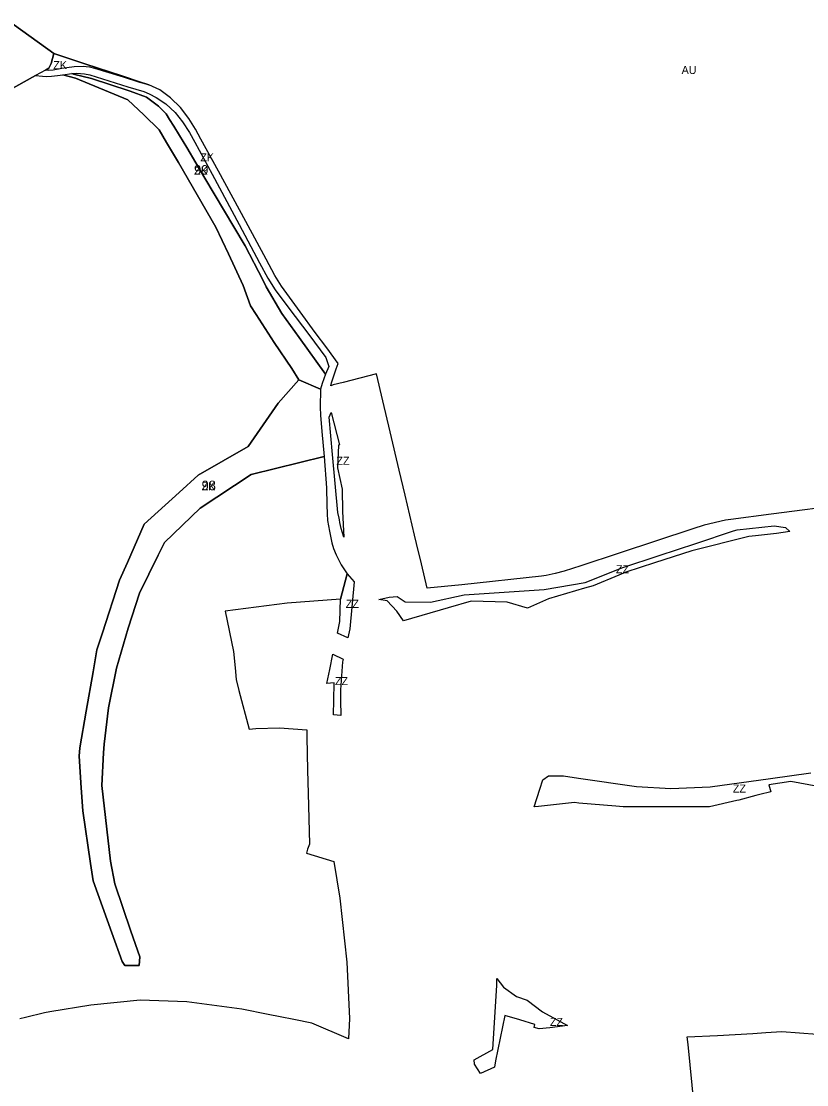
# Model space of a CAD drawing. Extents: x -535894 to -532834, y -1165802 to -1163647.
# Drawn here: x -534838 to -534347, y -1165127 to -1164462 of the extents above; entities that cross this region are included whole.
import ezdxf

# ---------------------------------------------------------------- set-up
doc = ezdxf.new("R2010")
doc.units = 0
for name, color, linetype in [('Vrstva 10', 7, 'Continuous'), ('Vrstva 16', 7, 'Continuous'), ('Vrstva 17', 7, 'Continuous'), ('Vrstva 19', 7, 'Continuous'), ('Vrstva 22', 7, 'Continuous'), ('Vrstva 61', 7, 'Continuous')]:
    doc.layers.add(name, color=color, linetype=linetype)

msp = doc.modelspace()

# ---------------------------------------------------------------- linework, layer by layer
at = {"layer": 'Vrstva 10'}
for points in [[(-534636.46, -1164784.72), (-534638.064, -1164779.14), (-534638.852, -1164775.393), (-534639.176, -1164773.814), (-534639.373, -1164772.852), (-534640.098, -1164769.323), (-534643.475, -1164733.089), (-534645.604, -1164709.726), (-534644.26, -1164706.72), (-534639.15, -1164726.91), (-534639.68, -1164727.13), (-534640.39, -1164741.43), (-534637.48, -1164754.64), (-534637.31, -1164768.51)], [(-534360.697, -1164778.681), (-534357.919, -1164781.042), (-534366.34, -1164782.38), (-534379.47, -1164783.81), (-534383.65, -1164784.27), (-534419.24, -1164793.21), (-534442.43, -1164800.73), (-534460.33, -1164806.54), (-534464.74, -1164808.35), (-534480.71, -1164814.95), (-534486.09, -1164816.51), (-534508.57, -1164823.07), (-534521.8, -1164828.99), (-534534.47, -1164825.11), (-534557.01, -1164824.52), (-534571.19, -1164828.66), (-534599.08, -1164836.8), (-534603.3, -1164830.84), (-534609.45, -1164824.46), (-534614.56, -1164823.48), (-534608.112, -1164822.093), (-534603.04, -1164821.677), (-534598.14, -1164825.08), (-534582.32, -1164825.13), (-534561.27, -1164820.66), (-534511.37, -1164817.22), (-534485.79, -1164812.88), (-534462.18, -1164803.59), (-534439.58, -1164796.11), (-534428.15, -1164792.33), (-534416.78, -1164788.57), (-534393.08, -1164780.73), (-534390.78, -1164779.97), (-534367.86, -1164777.52)], [(-534634.384, -1164807.473), (-534629.933, -1164812.5), (-534632.65, -1164841.86), (-534633.89, -1164847.539), (-534640.463, -1164844.555), (-534638.93, -1164837.28), (-534638.54, -1164823.25)], [(-534638.31, -1164895.93), (-534642.85, -1164895.55), (-534642.66, -1164886.34), (-534642.44, -1164875.67), (-534647.08, -1164876), (-534645.23, -1164867.21), (-534643.23, -1164857.71), (-534636.791, -1164860.825), (-534637.156, -1164862.496), (-534638.46, -1164879.942), (-534638.46, -1164886.69)], [(-534541.67, -1165111.7), (-534542.44, -1165115.58), (-534551, -1165119.46), (-534554.9, -1165113.66), (-534555.08, -1165111.1), (-534543.46, -1165104.62), (-534540.87, -1165064.35), (-534540.96, -1165060.2), (-534536.786, -1165065.584), (-534528.58, -1165071.39), (-534522.06, -1165073.71), (-534512.37, -1165081.09), (-534496.832, -1165089.669), (-534507.77, -1165091), (-534514.4, -1165091.6), (-534517.52, -1165090.78), (-534517.17, -1165088.92), (-534526.65, -1165086.13), (-534535.98, -1165083.39)]]:
    msp.add_lwpolyline(points, close=True, dxfattribs=at)
msp.add_lwpolyline([(-534334.97, -1164941.39), (-534357.43, -1164937.18), (-534371.08, -1164939.34), (-534369.96, -1164943.59), (-534376.73, -1164945.38), (-534379.25, -1164946.03), (-534389.78, -1164948.76), (-534391.17, -1164949.12), (-534408.23, -1164953), (-534422.33, -1164953), (-534431.79, -1164953.01), (-534436.16, -1164953), (-534443.26, -1164953), (-534445.31, -1164953), (-534462.09, -1164953), (-534466.57, -1164952.61), (-534489.63, -1164950.63), (-534492.39, -1164950.39), (-534514.81, -1164952.71), (-534517.7, -1164953.01), (-534513.989, -1164941.981), (-534512.197, -1164936.183), (-534508.626, -1164933.758), (-534499.188, -1164933.763), (-534489.849, -1164935.129), (-534453.798, -1164940.399), (-534432.188, -1164941.664), (-534407.72, -1164940.465), (-534369.994, -1164935.234), (-534344.906, -1164931.755)], dxfattribs=at)
at = {"layer": 'Vrstva 16'}
for points in [[(-534812.44, -1164492.038), (-534817.869, -1164493.052), (-534820.49, -1164493.143), (-534822.728, -1164493.033), (-534820.5, -1164491.79), (-534819.12, -1164488.91), (-534817.509, -1164482.62), (-534798.087, -1164488.983), (-534774.321, -1164496.768), (-534763.983, -1164500.339), (-534758.097, -1164502.081), (-534763.833, -1164500.668), (-534774.034, -1164497.362), (-534791.926, -1164491.894), (-534795.044, -1164491.154), (-534797.225, -1164490.889), (-534799.185, -1164490.795), (-534804.682, -1164491.006)], [(-534645.847, -1164677.959), (-534647.904, -1164682.84), (-534664.33, -1164659.93), (-534675.14, -1164644.85), (-534684.8, -1164628.21), (-534686.96, -1164624.01), (-534697.93, -1164602.7), (-534705.03, -1164590.78), (-534723.13, -1164560.41), (-534734.51, -1164541.31), (-534738.99, -1164533.78), (-534742.58, -1164527.98), (-534745.16, -1164523.82), (-534747.341, -1164520.291), (-534752.17, -1164515.41), (-534759.6, -1164509.93), (-534769.82, -1164506.09), (-534770.38, -1164505.88), (-534793.9, -1164498.24), (-534805.09, -1164495.48), (-534806.114, -1164495), (-534803.324, -1164494.852), (-534798.38, -1164495.209), (-534794.97, -1164495.874), (-534771.151, -1164503.333), (-534761.232, -1164506.36), (-534758.012, -1164507.727), (-534753.525, -1164510.08), (-534747.523, -1164514.089), (-534741.751, -1164519.514), (-534737.079, -1164525.158), (-534732.786, -1164531.828), (-534729.336, -1164538.044), (-534718.517, -1164558.022), (-534701.714, -1164589.354), (-534688.974, -1164613.292), (-534683.792, -1164622.823), (-534679.184, -1164630.139), (-534670.74, -1164641.717), (-534658.272, -1164658.05), (-534647.629, -1164672.429)]]:
    msp.add_lwpolyline(points, close=True, dxfattribs=at)
at = {"layer": 'Vrstva 17'}
for points in [[(-534650.975, -1164692.251), (-534664.512, -1164686.431), (-534668.831, -1164679.241), (-534679.849, -1164663.025), (-534691.158, -1164645.549), (-534694.624, -1164640.176), (-534699.325, -1164627.52), (-534708.387, -1164607.675), (-534716.225, -1164591.109), (-534739.693, -1164550.585), (-534747.026, -1164538.11), (-534751.669, -1164530.212), (-534761.268, -1164520.981), (-534771.301, -1164511.515), (-534803.86, -1164497.99), (-534811.888, -1164495.833), (-534806.114, -1164495), (-534805.09, -1164495.48), (-534793.9, -1164498.24), (-534770.38, -1164505.88), (-534769.82, -1164506.09), (-534759.6, -1164509.93), (-534752.17, -1164515.41), (-534747.341, -1164520.291), (-534745.16, -1164523.82), (-534742.58, -1164527.98), (-534738.99, -1164533.78), (-534734.51, -1164541.31), (-534723.13, -1164560.41), (-534705.03, -1164590.78), (-534697.93, -1164602.7), (-534686.96, -1164624.01), (-534684.8, -1164628.21), (-534675.14, -1164644.85), (-534664.33, -1164659.93), (-534647.904, -1164682.84), (-534649.925, -1164688.576)], [(-534650.975, -1164692.251), (-534651.253, -1164703.409), (-534651.057, -1164708.531), (-534650.184, -1164718.674), (-534648.645, -1164734.35), (-534694.357, -1164745.499), (-534726.198, -1164766.578), (-534748.337, -1164788.036), (-534752.217, -1164795.829), (-534764, -1164819.5), (-534770.97, -1164841.493), (-534778.305, -1164866.502), (-534783.275, -1164891.208), (-534786.064, -1164913.989), (-534786.534, -1164919.322), (-534787.471, -1164939.621), (-534782.087, -1164986.922), (-534779.471, -1165001.114), (-534769.351, -1165030.692), (-534763.686, -1165046.697), (-534764.195, -1165052.038), (-534773.14, -1165052.16), (-534774.871, -1165049.581), (-534781.343, -1165031.601), (-534792.975, -1164999.282), (-534794.582, -1164988.341), (-534799.405, -1164955.5), (-534800.386, -1164941.122), (-534801.727, -1164921.469), (-534801.157, -1164916.179), (-534797.183, -1164893.319), (-534792.919, -1164868.784), (-534790.508, -1164854.914), (-534787.074, -1164844.324), (-534776.399, -1164811.411), (-534771.546, -1164800.359), (-534761.063, -1164776.485), (-534739.279, -1164756.778), (-534727.363, -1164746), (-534696.12, -1164728), (-534677.488, -1164700.896), (-534664.512, -1164686.431)]]:
    msp.add_lwpolyline(points, close=True, dxfattribs=at)
at = {"layer": 'Vrstva 19'}
msp.add_lwpolyline([(-534866.733, -1164446.894), (-534817.509, -1164482.62), (-534819.12, -1164488.91), (-534820.5, -1164491.79), (-534822.728, -1164493.033), (-534828.796, -1164496.418), (-534893.74, -1164532.65), (-534906.91, -1164544.6), (-534916.57, -1164551.88), (-534926.03, -1164558.08), (-534936.2, -1164561.96), (-534946.31, -1164563.69), (-534957.79, -1164565.07), (-535001.64, -1164568.89), (-535054.61, -1164575.73), (-535101.2, -1164586.14), (-535117.95, -1164592.03), (-535326.28, -1164371.53)], dxfattribs=at)
at = {"layer": 'Vrstva 22'}
for points in [[(-534321.12, -1164763.995), (-534369.617, -1164770.285), (-534394.776, -1164773.547), (-534398.19, -1164773.99), (-534411.44, -1164777.13), (-534418.651, -1164779.505), (-534464.631, -1164794.65), (-534488.479, -1164802.488), (-534498.81, -1164805.87), (-534504.58, -1164807.36), (-534510.13, -1164808.51), (-534513.084, -1164808.974), (-534562.681, -1164814.447), (-534584.381, -1164816.448), (-534587.96, -1164801.37), (-534590.992, -1164788.561), (-534592.2, -1164783.46), (-534598.15, -1164758.42), (-534601.84, -1164742.85), (-534607.53, -1164718.9), (-534612.14, -1164699.44), (-534616.11, -1164682.7), (-534636.909, -1164687.961), (-534643.11, -1164689.53), (-534644.558, -1164690.047), (-534644.017, -1164688.264), (-534641.283, -1164679.593), (-534639.907, -1164676.108), (-534647.086, -1164666.492), (-534654.209, -1164656.789), (-534663.7, -1164643.954), (-534675.376, -1164627.896), (-534679.387, -1164621.172), (-534684.956, -1164611.107), (-534697.594, -1164587.582), (-534714.726, -1164556.06), (-534725.763, -1164536.1), (-534729.113, -1164529.776), (-534733.095, -1164523.114), (-534738.476, -1164516.319), (-534744.631, -1164510.374), (-534751.317, -1164505.211), (-534758.097, -1164502.081), (-534763.983, -1164500.339), (-534774.321, -1164496.768), (-534798.087, -1164488.983), (-534817.509, -1164482.62), (-534866.733, -1164446.894)], [(-534893.74, -1164532.65), (-534828.796, -1164496.418), (-534824.624, -1164496.838), (-534821.801, -1164496.902), (-534818.995, -1164496.791), (-534815.119, -1164496.425), (-534811.888, -1164495.833), (-534803.86, -1164497.99), (-534771.301, -1164511.515), (-534761.268, -1164520.981), (-534751.669, -1164530.212), (-534747.026, -1164538.11), (-534739.693, -1164550.585), (-534716.225, -1164591.109), (-534708.387, -1164607.675), (-534699.325, -1164627.52), (-534694.624, -1164640.176), (-534691.158, -1164645.549), (-534679.849, -1164663.025), (-534668.831, -1164679.241), (-534664.512, -1164686.431), (-534677.488, -1164700.896), (-534696.12, -1164728), (-534727.363, -1164746), (-534739.279, -1164756.778), (-534761.063, -1164776.485), (-534771.546, -1164800.359), (-534776.399, -1164811.411), (-534787.074, -1164844.324), (-534790.508, -1164854.914), (-534792.919, -1164868.784), (-534797.183, -1164893.319), (-534801.157, -1164916.179), (-534801.727, -1164921.469), (-534800.386, -1164941.122), (-534799.405, -1164955.5), (-534794.582, -1164988.341), (-534792.975, -1164999.282), (-534781.343, -1165031.601), (-534774.871, -1165049.581), (-534773.14, -1165052.16), (-534764.195, -1165052.038), (-534763.686, -1165046.697), (-534769.351, -1165030.692), (-534779.471, -1165001.114), (-534782.087, -1164986.922), (-534787.471, -1164939.621), (-534786.534, -1164919.322), (-534786.064, -1164913.989), (-534783.275, -1164891.208), (-534778.305, -1164866.502), (-534770.97, -1164841.493), (-534764, -1164819.5), (-534752.217, -1164795.829), (-534748.337, -1164788.036), (-534726.198, -1164766.578), (-534694.357, -1164745.499), (-534648.645, -1164734.35), (-534647.322, -1164753.718), (-534646.997, -1164764.497), (-534646.876, -1164770.138), (-534646.536, -1164774.156), (-534645.397, -1164780.979), (-534643.958, -1164788.253), (-534642.853, -1164791.65), (-534641.201, -1164795.663), (-534638.138, -1164801.982), (-534634.384, -1164807.473), (-534638.54, -1164823.25), (-534671.88, -1164825.83), (-534710.47, -1164830.87), (-534705.37, -1164856.07), (-534704.354, -1164866.213), (-534703.62, -1164873.54), (-534701.97, -1164880.31), (-534695.57, -1164904.53), (-534691.25, -1164904.07), (-534676.49, -1164903.74), (-534659.61, -1164905.01), (-534659.5, -1164909.46), (-534659.02, -1164930.05), (-534658.67, -1164944.77), (-534658.09, -1164968.25), (-534657.76, -1164976.32), (-534659.02, -1164979.39), (-534659.81, -1164981.95), (-534642.59, -1164987.17), (-534638.87, -1165010.05), (-534634.53, -1165050.1), (-534632.91, -1165085.29), (-534633.52, -1165097.84), (-534656.31, -1165088.09), (-534667.56, -1165085.84), (-534676.08, -1165084.13), (-534683.71, -1165082.61), (-534700.02, -1165079.35), (-534734.34, -1165074.8), (-534763.47, -1165073.76), (-534794.45, -1165076.97), (-534819.92, -1165081.13), (-534823.22, -1165081.65), (-534835.13, -1165084.593), (-534838.685, -1165085.472)], [(-534340.36, -1165276.59), (-534348.28, -1165269.23), (-534358.8, -1165260.74), (-534363.2, -1165257.26), (-534368.13, -1165254.92), (-534376.79, -1165251.88), (-534386.06, -1165251.44), (-534389.65, -1165251.4), (-534397.29, -1165252.4), (-534405.45, -1165253.73), (-534408.79, -1165228.57), (-534416.26, -1165154.3), (-534420.23, -1165114.18), (-534421.45, -1165101.43), (-534422.065, -1165096.672), (-534422.065, -1165096.672), (-534403.258, -1165095.841), (-534381.169, -1165094.484), (-534372.898, -1165093.976), (-534362.94, -1165093.25), (-534340.945, -1165094.96)]]:
    msp.add_lwpolyline(points, dxfattribs=at)

# ---------------------------------------------------------------- texts
at = {"layer": 'Vrstva 10'}
for rotation, p in [(0.0000001, (-534641.032, -1164739.3878)), (0, (-534466.5468, -1164807.16)), (0, (-534635.198, -1164828.7542)), (360, (-534641.9355, -1164876.9814)), (0.0000001, (-534393.57, -1164944.0844)), (360, (-534507.7482, -1165089.83))]:
    msp.add_text('ZZ', height=5, rotation=rotation, dxfattribs=at).set_placement(p)
at = {"layer": 'Vrstva 16'}
for rotation, p in [(0, (-534817.8089, -1164492.3505)), (360, (-534725.9805, -1164549.933))]:
    msp.add_text('ZK', height=5, rotation=rotation, dxfattribs=at).set_placement(p)
at = {"layer": 'Vrstva 17'}
for rotation, p in [(0, (-534729.896, -1164558.2781)), (360, (-534725.186, -1164755.3269))]:
    msp.add_text('ZK', height=5, rotation=rotation, dxfattribs=at).set_placement(p)
at = {"layer": 'Vrstva 22'}
msp.add_text('AU', height=5, rotation=0, dxfattribs=at).set_placement((-534425.5615, -1164495.384))
at = {"layer": 'Vrstva 61'}
for s, rotation, p in [('99', 0, (-534729.896, -1164558.2781)), ('98', 360, (-534725.186, -1164755.3269))]:
    msp.add_text(s, height=6, rotation=rotation, dxfattribs=at).set_placement(p)

doc.saveas('drawing.dxf')
